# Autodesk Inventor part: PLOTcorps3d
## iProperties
Author: ajt
Created: 2001-10
Part Number: PLOTcorps3d
Material: Par défaut
Document SubType Name: Proxy Part
Designer: ajt
Control State: 0
Master: False
Checked Out: False
PropertySet Name: Design Tracking Control
Shininess: 21.0
PropertySet Name: _Private Model Information
Length Units: 11269
Angle Units: 11283
Time Units: 11279
Mass Units: 11290
Length Display Precision: 3
Angle Display Precision: 2
Compacted: False
Density: 0.0
Volumn: 0.0
Area: 0.0
PropertySet Name: Model Information
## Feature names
1. LinkedPart1
